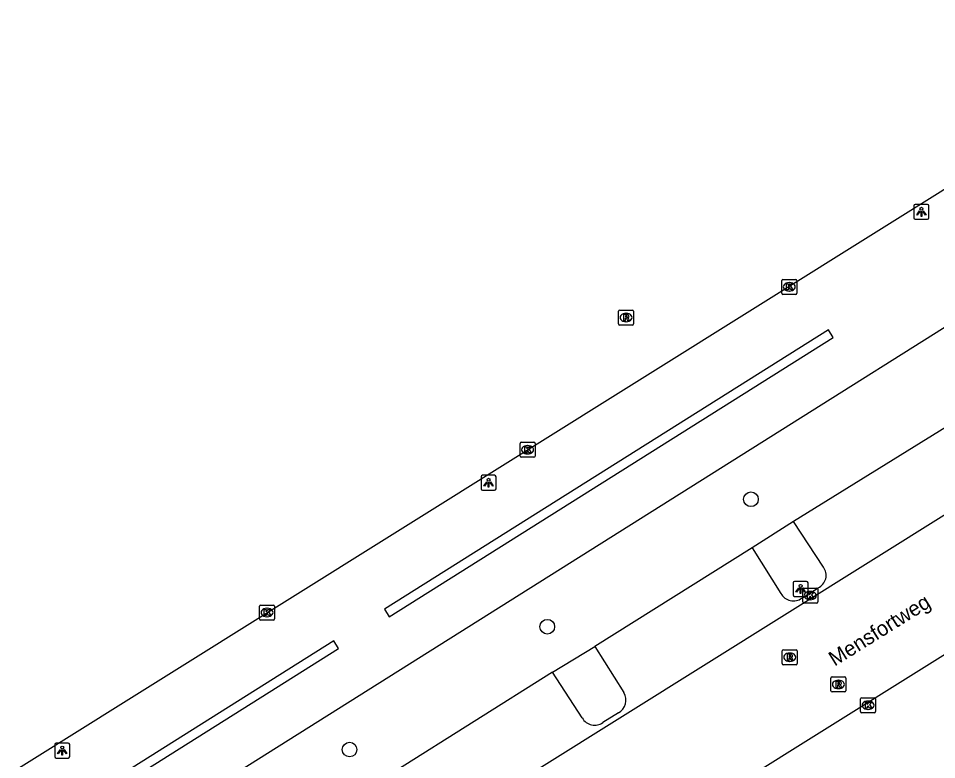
# Model space of a CAD drawing. Extents: x 158461 to 159795, y 387220 to 388672.
# Drawn here: x 158601.3 to 158662.6, y 387954.6 to 388004 of the extents above; entities that cross this region are included whole.
import ezdxf

# ---------------------------------------------------------------- set-up
doc = ezdxf.new("R2010")
doc.units = 0
for name, color, linetype in [('IMGEO_Boom', 7, 'Continuous'), ('IMGEO_Groenvoorziening', 7, 'Continuous'), ('IMGEO_Haag', 7, 'Continuous'), ('IMGEO_Kolk', 7, 'Continuous'), ('IMGEO_Lichtpunt', 7, 'Continuous'), ('IMGEO_Openbare_ruimte_label', 7, 'Continuous'), ('IMGEO_Parkeervlak_open', 7, 'Continuous'), ('IMGEO_Rijbaan_lokaal_gesloten', 7, 'Continuous'), ('IMGEO_Rioolput', 7, 'Continuous')]:
    doc.layers.add(name, color=color, linetype=linetype)

msp = doc.modelspace()

# ---------------------------------------------------------------- linework, layer by layer
at = {"layer": 'IMGEO_Boom'}
for centre in [(158650.157, 387971.942), (158636.568, 387963.44), (158623.371, 387955.25)]:
    msp.add_circle(centre, 0.489, dxfattribs=at)
at = {"layer": 'IMGEO_Groenvoorziening'}
for points in [[(158682.361, 388002.322), (158681.495, 388001.799), (158681.34, 388000), (158681.403, 387998.044), (158681.503, 387994.979), (158681.122, 387994.739), (158591.006, 387938.082)], [(158652.994, 387970.461), (158650.237, 387968.707)], [(158636.923, 387960.416), (158639.743, 387962.124)]]:
    msp.add_lwpolyline(points, dxfattribs=at)
at = {"layer": 'IMGEO_Haag'}
for points in [[(158626.021, 387964.112), (158655.652, 387982.741), (158655.332, 387983.249), (158625.701, 387964.62), (158626.021, 387964.112)], [(158590.888, 387942.023), (158622.635, 387961.983), (158622.315, 387962.491), (158590.568, 387942.531), (158590.888, 387942.023)]]:
    msp.add_lwpolyline(points, dxfattribs=at)
at = {"layer": 'IMGEO_Kolk'}
for p, q in [((158652.217, 387985.688), (158652.217, 387986.54)), ((158652.292, 387986.614), (158653.144, 387986.614)), ((158653.218, 387986.54), (158653.218, 387985.688)), ((158652.728, 387985.834), (158652.703, 387985.834)), ((158652.705, 387986.394), (158652.73, 387986.394)), ((158653.144, 387985.614), (158652.292, 387985.614)), ((158634.751, 387974.823), (158634.751, 387975.675)), ((158634.826, 387975.749), (158635.678, 387975.749)), ((158635.239, 387975.529), (158635.264, 387975.529)), ((158635.752, 387975.675), (158635.752, 387974.823)), ((158635.262, 387974.969), (158635.237, 387974.969)), ((158635.678, 387974.749), (158634.826, 387974.749)), ((158653.613, 387965.094), (158653.613, 387965.946)), ((158653.688, 387966.02), (158654.54, 387966.02)), ((158654.101, 387965.8), (158654.126, 387965.8)), ((158654.614, 387965.946), (158654.614, 387965.094)), ((158654.54, 387965.02), (158653.688, 387965.02)), ((158654.124, 387965.24), (158654.099, 387965.24)), ((158617.361, 387963.964), (158617.361, 387964.816)), ((158617.436, 387964.89), (158618.288, 387964.89)), ((158617.849, 387964.67), (158617.874, 387964.67)), ((158618.362, 387964.816), (158618.362, 387963.964)), ((158618.288, 387963.89), (158617.436, 387963.89)), ((158617.872, 387964.11), (158617.847, 387964.11)), ((158657.475, 387957.777), (158657.475, 387958.629)), ((158657.55, 387958.703), (158658.402, 387958.703)), ((158657.963, 387958.483), (158657.988, 387958.483)), ((158658.476, 387958.629), (158658.476, 387957.777)), ((158658.402, 387957.703), (158657.55, 387957.703)), ((158657.986, 387957.923), (158657.961, 387957.923))]:
    msp.add_line(p, q, dxfattribs=at)
for points in [[(158652.217, 387985.688), (158652.217, 387986.54)], [(158652.292, 387986.614), (158653.144, 387986.614)], [(158653.218, 387986.54), (158653.218, 387985.688)], [(158652.538, 387986.314), (158652.661, 387986.314), (158652.661, 387986.163), (158652.791, 387986.314), (158652.955, 387986.314), (158652.809, 387986.163), (158652.962, 387985.914), (158652.81, 387985.914), (158652.725, 387986.078), (158652.661, 387986.011), (158652.661, 387985.914), (158652.538, 387985.914), (158652.538, 387986.314)], [(158653.144, 387985.614), (158652.292, 387985.614)], [(158634.751, 387974.823), (158634.751, 387975.675)], [(158634.826, 387975.749), (158635.678, 387975.749)], [(158635.072, 387975.449), (158635.195, 387975.449), (158635.195, 387975.298), (158635.325, 387975.449), (158635.489, 387975.449), (158635.343, 387975.298), (158635.496, 387975.049), (158635.344, 387975.049), (158635.259, 387975.213), (158635.195, 387975.146), (158635.195, 387975.049), (158635.072, 387975.049), (158635.072, 387975.449)], [(158635.752, 387975.675), (158635.752, 387974.823)], [(158635.678, 387974.749), (158634.826, 387974.749)], [(158653.613, 387965.094), (158653.613, 387965.946)], [(158653.688, 387966.02), (158654.54, 387966.02)], [(158653.934, 387965.72), (158654.057, 387965.72), (158654.057, 387965.569), (158654.187, 387965.72), (158654.351, 387965.72), (158654.205, 387965.569), (158654.358, 387965.32), (158654.206, 387965.32), (158654.121, 387965.484), (158654.057, 387965.417), (158654.057, 387965.32), (158653.934, 387965.32), (158653.934, 387965.72)], [(158654.614, 387965.946), (158654.614, 387965.094)], [(158654.54, 387965.02), (158653.688, 387965.02)], [(158617.361, 387963.964), (158617.361, 387964.816)], [(158617.436, 387964.89), (158618.288, 387964.89)], [(158617.682, 387964.59), (158617.805, 387964.59), (158617.805, 387964.439), (158617.935, 387964.59), (158618.099, 387964.59), (158617.953, 387964.439), (158618.106, 387964.19), (158617.954, 387964.19), (158617.869, 387964.354), (158617.805, 387964.287), (158617.805, 387964.19), (158617.682, 387964.19), (158617.682, 387964.59)], [(158618.362, 387964.816), (158618.362, 387963.964)], [(158618.288, 387963.89), (158617.436, 387963.89)], [(158657.475, 387957.777), (158657.475, 387958.629)], [(158657.55, 387958.703), (158658.402, 387958.703)], [(158657.796, 387958.403), (158657.919, 387958.403), (158657.919, 387958.252), (158658.049, 387958.403), (158658.213, 387958.403), (158658.067, 387958.252), (158658.22, 387958.003), (158658.068, 387958.003), (158657.983, 387958.167), (158657.919, 387958.1), (158657.919, 387958.003), (158657.796, 387958.003), (158657.796, 387958.403)], [(158658.476, 387958.629), (158658.476, 387957.777)], [(158658.402, 387957.703), (158657.55, 387957.703)]]:
    msp.add_lwpolyline(points, dxfattribs=at)
for centre, start, end in [((158652.294, 387986.538), 91.55205, 178.44795), ((158652.294, 387986.538), 91.55205, 178.44795), ((158653.142, 387986.538), 1.55205, 88.44795), ((158653.142, 387986.538), 1.55205, 88.44795), ((158652.294, 387985.69), 181.55205, 268.44795), ((158652.294, 387985.69), 181.55205, 268.44795), ((158653.142, 387985.69), 271.55205, 358.44795), ((158653.142, 387985.69), 271.55205, 358.44795), ((158634.828, 387975.673), 91.55205, 178.44795), ((158634.828, 387975.673), 91.55205, 178.44795), ((158635.676, 387975.673), 1.55205, 88.44795), ((158635.676, 387975.673), 1.55205, 88.44795), ((158634.828, 387974.825), 181.55205, 268.44795), ((158634.828, 387974.825), 181.55205, 268.44795), ((158635.676, 387974.825), 271.55205, 358.44795), ((158635.676, 387974.825), 271.55205, 358.44795), ((158653.69, 387965.944), 91.55205, 178.44795), ((158653.69, 387965.944), 91.55205, 178.44795), ((158654.538, 387965.944), 1.55205, 88.44795), ((158654.538, 387965.944), 1.55205, 88.44795), ((158653.69, 387965.096), 181.55205, 268.44795), ((158653.69, 387965.096), 181.55205, 268.44795), ((158654.538, 387965.096), 271.55205, 358.44795), ((158654.538, 387965.096), 271.55205, 358.44795), ((158617.438, 387964.814), 91.55205, 178.44795), ((158617.438, 387964.814), 91.55205, 178.44795), ((158618.286, 387964.814), 1.55205, 88.44795), ((158618.286, 387964.814), 1.55205, 88.44795), ((158617.438, 387963.966), 181.55205, 268.44795), ((158617.438, 387963.966), 181.55205, 268.44795), ((158618.286, 387963.966), 271.55205, 358.44795), ((158618.286, 387963.966), 271.55205, 358.44795), ((158657.552, 387958.627), 91.55205, 178.44795), ((158657.552, 387958.627), 91.55205, 178.44795), ((158658.4, 387958.627), 1.55205, 88.44795), ((158658.4, 387958.627), 1.55205, 88.44795), ((158657.552, 387957.779), 181.55205, 268.44795), ((158657.552, 387957.779), 181.55205, 268.44795), ((158658.4, 387957.779), 271.55205, 358.44795), ((158658.4, 387957.779), 271.55205, 358.44795)]:
    msp.add_arc(centre, 0.0765, start, end, dxfattribs=at)
for centre, major_axis, ratio, start_param, end_param in [((158652.704, 387986.114), (-0.387, 0.002), 0.722429, 4.712389, 7.853982), ((158652.729, 387986.114), (-0.39, 0.002), 0.717154, 1.570796, 4.712389), ((158635.238, 387975.249), (-0.387, 0.002), 0.722429, 4.712389, 7.853982), ((158635.263, 387975.249), (-0.39, 0.002), 0.717154, 1.570796, 4.712389), ((158654.1, 387965.52), (-0.387, 0.002), 0.722429, 4.712389, 7.853982), ((158654.125, 387965.52), (-0.39, 0.002), 0.717154, 1.570796, 4.712389), ((158617.848, 387964.39), (-0.387, 0.002), 0.722429, 4.712389, 7.853982), ((158617.873, 387964.39), (-0.39, 0.002), 0.717154, 1.570796, 4.712389), ((158657.962, 387958.203), (-0.387, 0.002), 0.722429, 4.712389, 7.853982), ((158657.987, 387958.203), (-0.39, 0.002), 0.717154, 1.570796, 4.712389)]:
    msp.add_ellipse(centre, major_axis=major_axis, ratio=ratio, start_param=start_param, end_param=end_param, dxfattribs=at)
at = {"layer": 'IMGEO_Lichtpunt'}
for p, q in [((158661.035, 387991.523), (158661.035, 387990.716)), ((158661.035, 387991.523), (158661.035, 387990.716)), ((158661.937, 387991.618), (158661.129, 387991.618)), ((158661.937, 387991.618), (158661.129, 387991.618)), ((158662.031, 387990.716), (158662.031, 387991.523)), ((158662.031, 387990.716), (158662.031, 387991.523)), ((158661.129, 387990.622), (158661.937, 387990.622)), ((158661.129, 387990.622), (158661.937, 387990.622)), ((158632.151, 387973.446), (158632.151, 387972.639)), ((158632.151, 387973.446), (158632.151, 387972.639)), ((158633.053, 387973.541), (158632.245, 387973.541)), ((158633.053, 387973.541), (158632.245, 387973.541)), ((158633.147, 387972.639), (158633.147, 387973.446)), ((158633.147, 387972.639), (158633.147, 387973.446)), ((158632.245, 387972.545), (158633.053, 387972.545)), ((158632.245, 387972.545), (158633.053, 387972.545)), ((158652.975, 387966.368), (158652.975, 387965.561)), ((158652.975, 387966.368), (158652.975, 387965.561)), ((158653.877, 387966.463), (158653.069, 387966.463)), ((158653.877, 387966.463), (158653.069, 387966.463)), ((158653.971, 387965.561), (158653.971, 387966.368)), ((158653.971, 387965.561), (158653.971, 387966.368)), ((158653.069, 387965.467), (158653.877, 387965.467)), ((158653.069, 387965.467), (158653.877, 387965.467)), ((158603.699, 387955.581), (158603.699, 387954.774)), ((158603.699, 387955.581), (158603.699, 387954.774)), ((158604.601, 387955.676), (158603.793, 387955.676)), ((158604.601, 387955.676), (158603.793, 387955.676)), ((158604.695, 387954.774), (158604.695, 387955.581)), ((158604.695, 387954.774), (158604.695, 387955.581)), ((158603.793, 387954.68), (158604.601, 387954.68)), ((158603.793, 387954.68), (158604.601, 387954.68))]:
    msp.add_line(p, q, dxfattribs=at)
for points in [[(158661.409, 387991.187), (158661.448, 387991.159), (158661.26, 387990.897), (158661.222, 387990.924), (158661.409, 387991.187)], [(158661.511, 387991.139), (158661.558, 387991.139), (158661.558, 387990.817), (158661.511, 387990.817), (158661.511, 387991.139)], [(158661.621, 387991.159), (158661.659, 387991.186), (158661.846, 387990.924), (158661.807, 387990.896), (158661.621, 387991.159)], [(158632.525, 387973.11), (158632.564, 387973.082), (158632.376, 387972.82), (158632.338, 387972.847), (158632.525, 387973.11)], [(158632.627, 387973.062), (158632.674, 387973.062), (158632.674, 387972.74), (158632.627, 387972.74), (158632.627, 387973.062)], [(158632.737, 387973.082), (158632.775, 387973.109), (158632.962, 387972.847), (158632.923, 387972.819), (158632.737, 387973.082)], [(158653.349, 387966.032), (158653.388, 387966.004), (158653.2, 387965.742), (158653.162, 387965.769), (158653.349, 387966.032)], [(158653.451, 387965.984), (158653.498, 387965.984), (158653.498, 387965.662), (158653.451, 387965.662), (158653.451, 387965.984)], [(158653.561, 387966.004), (158653.599, 387966.031), (158653.786, 387965.769), (158653.747, 387965.741), (158653.561, 387966.004)], [(158604.073, 387955.245), (158604.112, 387955.217), (158603.924, 387954.955), (158603.886, 387954.982), (158604.073, 387955.245)], [(158604.175, 387955.197), (158604.222, 387955.197), (158604.222, 387954.875), (158604.175, 387954.875), (158604.175, 387955.197)], [(158604.285, 387955.217), (158604.323, 387955.244), (158604.51, 387954.982), (158604.471, 387954.954), (158604.285, 387955.217)]]:
    msp.add_lwpolyline(points, dxfattribs=at)
for centre in [(158661.534, 387991.321), (158632.65, 387973.244), (158653.474, 387966.166), (158604.198, 387955.379)]:
    msp.add_circle(centre, 0.0994, dxfattribs=at)
for centre, start, end in [((158661.129, 387991.523), 90, 180), ((158661.129, 387991.523), 90, 180), ((158661.937, 387991.523), 0, 90), ((158661.937, 387991.523), 0, 90), ((158661.129, 387990.716), 180, 270), ((158661.129, 387990.716), 180, 270), ((158661.937, 387990.716), 270, 0), ((158661.937, 387990.716), 270, 360), ((158632.245, 387973.446), 90, 180), ((158632.245, 387973.446), 90, 180), ((158633.053, 387973.446), 0, 90), ((158633.053, 387973.446), 0, 90), ((158632.245, 387972.639), 180, 270), ((158632.245, 387972.639), 180, 270), ((158633.053, 387972.639), 270, 0), ((158633.053, 387972.639), 270, 360), ((158653.069, 387966.368), 90, 180), ((158653.069, 387966.368), 90, 180), ((158653.877, 387966.368), 0, 90), ((158653.877, 387966.368), 0, 90), ((158653.069, 387965.561), 180, 270), ((158653.069, 387965.561), 180, 270), ((158653.877, 387965.561), 270, 0), ((158653.877, 387965.561), 270, 360), ((158603.793, 387955.581), 90, 180), ((158603.793, 387955.581), 90, 180), ((158604.601, 387955.581), 0, 90), ((158604.601, 387955.581), 0, 90), ((158603.793, 387954.774), 180, 270), ((158603.793, 387954.774), 180, 270), ((158604.601, 387954.774), 270, 0), ((158604.601, 387954.774), 270, 360)]:
    msp.add_arc(centre, 0.0946, start, end, dxfattribs=at)
at = {"layer": 'IMGEO_Parkeervlak_open'}
for points in [[(158663.669, 387977.074), (158652.994, 387970.461)], [(158654.993, 387967.42), (158652.994, 387970.461)], [(158650.237, 387968.707), (158639.743, 387962.124)], [(158650.237, 387968.707), (158652.163, 387965.667)], [(158653.556, 387965.35), (158654.645, 387966.031)], [(158639.743, 387962.124), (158641.683, 387959.045)], [(158636.923, 387960.416), (158626.454, 387953.83)], [(158638.901, 387957.357), (158636.923, 387960.416)], [(158641.312, 387957.688), (158640.279, 387957.05)]]:
    msp.add_lwpolyline(points, dxfattribs=at)
for centre, radius, start, end in [((158654.256, 387966.867), 0.922, 294.98311, 36.88618), ((158652.992, 387966.091), 0.931, 207.07043, 307.28904), ((158640.814, 387958.553), 0.999, 299.92876, 29.48956), ((158639.728, 387957.822), 0.949, 209.35297, 305.52779)]:
    msp.add_arc(centre, radius, start, end, dxfattribs=at)
at = {"layer": 'IMGEO_Rijbaan_lokaal_gesloten'}
for points in [[(158586.704, 387944.915), (158674.848, 388000), (158679.799, 388003.099), (158680.443, 388003.507), (158681.258, 388004.023)], [(158614.197, 387940.345), (158690.944, 387988.345)], [(158693.899, 387980.837), (158616.755, 387932.616), (158615.34, 387931.575)]]:
    msp.add_lwpolyline(points, dxfattribs=at)
at = {"layer": 'IMGEO_Rioolput'}
for p, q in [((158641.325, 387983.642), (158641.325, 387984.494)), ((158641.4, 387984.568), (158642.252, 387984.568)), ((158641.813, 387984.348), (158641.838, 387984.348)), ((158642.326, 387984.494), (158642.326, 387983.642)), ((158642.252, 387983.568), (158641.4, 387983.568)), ((158641.836, 387983.788), (158641.811, 387983.788)), ((158652.246, 387960.98), (158652.246, 387961.832)), ((158652.321, 387961.906), (158653.173, 387961.906)), ((158652.734, 387961.686), (158652.759, 387961.686)), ((158653.247, 387961.832), (158653.247, 387960.98)), ((158653.173, 387960.906), (158652.321, 387960.906)), ((158652.757, 387961.126), (158652.732, 387961.126)), ((158655.496, 387959.168), (158655.496, 387960.02)), ((158655.571, 387960.094), (158656.423, 387960.094)), ((158655.984, 387959.874), (158656.009, 387959.874)), ((158656.497, 387960.02), (158656.497, 387959.168)), ((158656.423, 387959.094), (158655.571, 387959.094)), ((158656.007, 387959.314), (158655.982, 387959.314))]:
    msp.add_line(p, q, dxfattribs=at)
for points in [[(158641.325, 387983.642), (158641.325, 387984.494)], [(158641.4, 387984.568), (158642.252, 387984.568)], [(158641.914, 387984.266), (158641.662, 387984.268), (158641.662, 387983.868)], [(158641.662, 387983.868), (158641.786, 387983.868), (158641.786, 387984.03), (158641.797, 387984.03)], [(158641.84, 387984.187), (158641.786, 387984.187), (158641.786, 387984.106)], [(158641.786, 387984.106), (158641.838, 387984.106)], [(158641.844, 387984.001), (158641.915, 387983.868), (158642.055, 387983.868), (158641.99, 387983.994)], [(158642.326, 387984.494), (158642.326, 387983.642)], [(158642.252, 387983.568), (158641.4, 387983.568)], [(158652.246, 387960.98), (158652.246, 387961.832)], [(158652.321, 387961.906), (158653.173, 387961.906)], [(158652.835, 387961.604), (158652.583, 387961.606), (158652.583, 387961.206)], [(158652.583, 387961.206), (158652.707, 387961.206), (158652.707, 387961.368), (158652.718, 387961.368)], [(158652.761, 387961.525), (158652.707, 387961.525), (158652.707, 387961.444)], [(158652.707, 387961.444), (158652.759, 387961.444)], [(158652.765, 387961.339), (158652.836, 387961.206), (158652.976, 387961.206), (158652.911, 387961.332)], [(158653.247, 387961.832), (158653.247, 387960.98)], [(158653.173, 387960.906), (158652.321, 387960.906)], [(158655.496, 387959.168), (158655.496, 387960.02)], [(158655.571, 387960.094), (158656.423, 387960.094)], [(158656.085, 387959.792), (158655.833, 387959.794), (158655.833, 387959.394)], [(158655.833, 387959.394), (158655.957, 387959.394), (158655.957, 387959.556), (158655.968, 387959.556)], [(158656.011, 387959.713), (158655.957, 387959.713), (158655.957, 387959.632)], [(158655.957, 387959.632), (158656.009, 387959.632)], [(158656.015, 387959.527), (158656.086, 387959.394), (158656.226, 387959.394), (158656.161, 387959.52)], [(158656.497, 387960.02), (158656.497, 387959.168)], [(158656.423, 387959.094), (158655.571, 387959.094)]]:
    msp.add_lwpolyline(points, dxfattribs=at)
for centre, radius, start, end in [((158641.402, 387984.492), 0.0765, 91.55205, 178.44795), ((158641.402, 387984.492), 0.0765, 91.55205, 178.44795), ((158641.796, 387983.977), 0.0533, 26.02933, 88.69889), ((158641.822, 387984.295), 0.19, 274.7715, 282.96867), ((158641.846, 387984.091), 0.0964, 77.00612, 93.18647), ((158641.86, 387984.148), 0.0378, 276.66336, 79.67722), ((158641.913, 387984.156), 0.109, 350.36119, 89.41601), ((158641.911, 387984.156), 0.112, 277.58423, 350.98172), ((158641.895, 387983.941), 0.108, 29.51342, 73.79051), ((158642.25, 387984.492), 0.0765, 1.55205, 88.44795), ((158642.25, 387984.492), 0.0765, 1.55205, 88.44795), ((158641.402, 387983.644), 0.0765, 181.55205, 268.44795), ((158641.402, 387983.644), 0.0765, 181.55205, 268.44795), ((158642.25, 387983.644), 0.0765, 271.55205, 358.44795), ((158642.25, 387983.644), 0.0765, 271.55205, 358.44795), ((158652.323, 387961.83), 0.0765, 91.55205, 178.44795), ((158652.323, 387961.83), 0.0765, 91.55205, 178.44795), ((158652.717, 387961.315), 0.0533, 26.02933, 88.69889), ((158652.743, 387961.633), 0.19, 274.7715, 282.96867), ((158652.767, 387961.429), 0.0964, 77.00612, 93.18647), ((158652.781, 387961.486), 0.0378, 276.66336, 79.67722), ((158652.834, 387961.494), 0.109, 350.36119, 89.41601), ((158652.832, 387961.494), 0.112, 277.58423, 350.98172), ((158652.816, 387961.279), 0.108, 29.51342, 73.79051), ((158653.171, 387961.83), 0.0765, 1.55205, 88.44795), ((158653.171, 387961.83), 0.0765, 1.55205, 88.44795), ((158652.323, 387960.982), 0.0765, 181.55205, 268.44795), ((158652.323, 387960.982), 0.0765, 181.55205, 268.44795), ((158653.171, 387960.982), 0.0765, 271.55205, 358.44795), ((158653.171, 387960.982), 0.0765, 271.55205, 358.44795), ((158655.573, 387960.018), 0.0765, 91.55205, 178.44795), ((158655.573, 387960.018), 0.0765, 91.55205, 178.44795), ((158655.967, 387959.503), 0.0533, 26.02933, 88.69889), ((158655.993, 387959.821), 0.19, 274.7715, 282.96867), ((158656.017, 387959.617), 0.0964, 77.00612, 93.18647), ((158656.031, 387959.674), 0.0378, 276.66336, 79.67722), ((158656.084, 387959.682), 0.109, 350.36119, 89.41601), ((158656.082, 387959.682), 0.112, 277.58423, 350.98172), ((158656.066, 387959.467), 0.108, 29.51342, 73.79051), ((158656.421, 387960.018), 0.0765, 1.55205, 88.44795), ((158656.421, 387960.018), 0.0765, 1.55205, 88.44795), ((158655.573, 387959.17), 0.0765, 181.55205, 268.44795), ((158655.573, 387959.17), 0.0765, 181.55205, 268.44795), ((158656.421, 387959.17), 0.0765, 271.55205, 358.44795), ((158656.421, 387959.17), 0.0765, 271.55205, 358.44795)]:
    msp.add_arc(centre, radius, start, end, dxfattribs=at)
for centre, major_axis, ratio, start_param, end_param in [((158641.812, 387984.068), (-0.387, 0.002), 0.722429, 4.712389, 7.853982), ((158641.837, 387984.068), (-0.39, 0.002), 0.717154, 1.570796, 4.712389), ((158652.733, 387961.406), (-0.387, 0.002), 0.722429, 4.712389, 7.853982), ((158652.758, 387961.406), (-0.39, 0.002), 0.717154, 1.570796, 4.712389), ((158655.983, 387959.594), (-0.387, 0.002), 0.722429, 4.712389, 7.853982), ((158656.008, 387959.594), (-0.39, 0.002), 0.717154, 1.570796, 4.712389)]:
    msp.add_ellipse(centre, major_axis=major_axis, ratio=ratio, start_param=start_param, end_param=end_param, dxfattribs=at)

# ---------------------------------------------------------------- texts
at = {"layer": 'IMGEO_Openbare_ruimte_label'}
msp.add_text('Mensfortweg', height=1, rotation=31.92646, dxfattribs=at).set_placement((158655.743, 387960.773))

doc.saveas('drawing.dxf')
